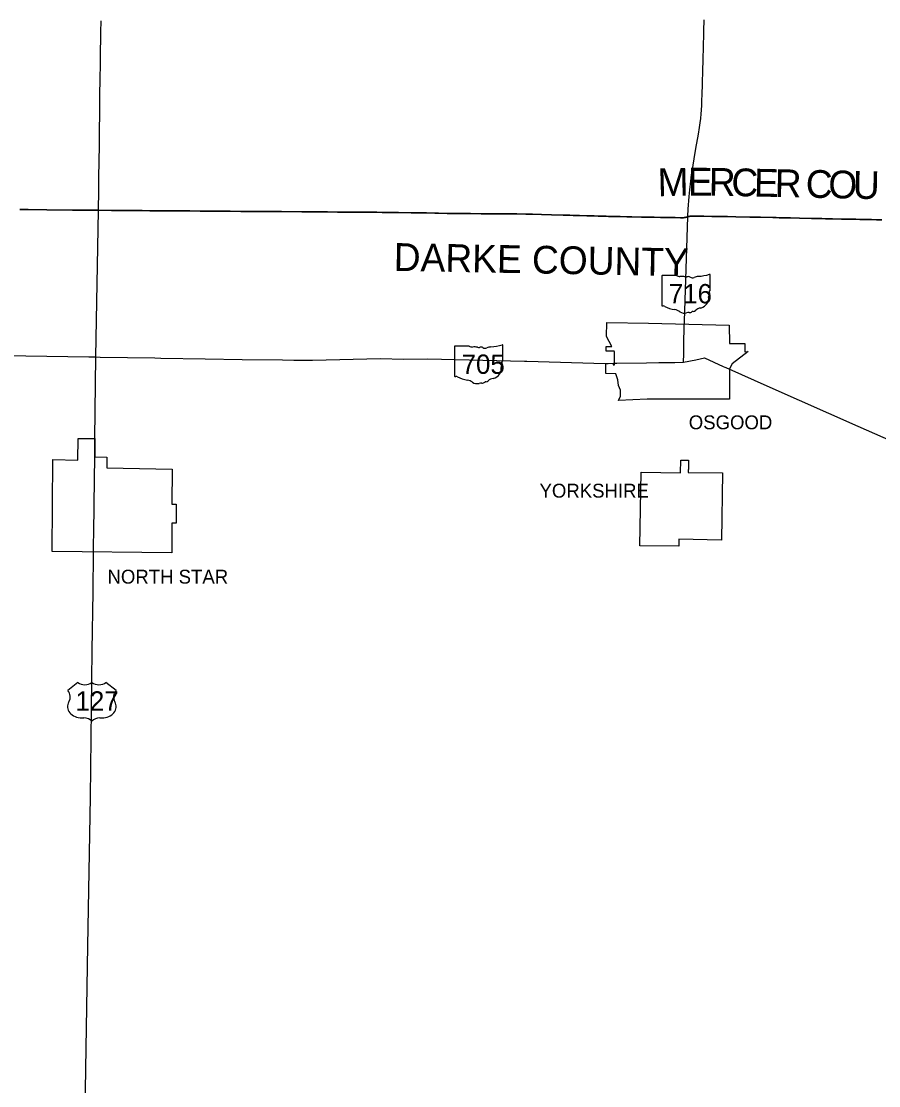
# Model space of a CAD drawing. Extents: x 0 to 34, y 0 to 22.
# Drawn here: x 3.621 to 4.117, y 18.175 to 18.791 of the extents above; entities that cross this region are included whole.
import ezdxf

# ---------------------------------------------------------------- set-up
doc = ezdxf.new("R2010")
doc.units = 0
for name, color, linetype in [('GM_X_Corporation', 7, 'Continuous'), ('GM_X_Corporation_Text', 7, 'Continuous'), ('GM_X_County', 7, 'Continuous'), ('GM_X_County_Text', 7, 'Continuous'), ('GM_X_State_Location', 7, 'Continuous'), ('GM_X_State_Route', 7, 'Continuous'), ('GM_X_State_Shield', 7, 'Continuous'), ('GM_X_US_Location', 7, 'Continuous'), ('GM_X_US_Route', 7, 'Continuous'), ('GM_X_US_Shield', 7, 'Continuous')]:
    doc.layers.add(name, color=color, linetype=linetype)

msp = doc.modelspace()

# ---------------------------------------------------------------- linework, layer by layer
at = {"layer": 'GM_X_Corporation'}
for points in [[(4.03961, 18.60404), (4.03961, 18.59925), (4.04143, 18.59956), (4.03216, 18.59229), (4.03063, 18.58941), (4.0307, 18.57198), (3.98295, 18.57181), (3.96632, 18.57122), (3.96758, 18.57369), (3.96764, 18.57718), (3.96634, 18.57985), (3.96604, 18.58315), (3.96488, 18.58654), (3.959, 18.58684), (3.95899, 18.59261), (3.96338, 18.59269), (3.9634, 18.59175), (3.96404, 18.59178), (3.96403, 18.59269), (3.96404, 18.59925), (3.96381, 18.59971), (3.96386, 18.59961), (3.95927, 18.59968), (3.95931, 18.60235), (3.96246, 18.60232), (3.95948, 18.60811), (3.95961, 18.61624), (3.98373, 18.61586), (4.03054, 18.61482), (4.03058, 18.6042)], [(3.67022, 18.53837), (3.67017, 18.53219), (3.70789, 18.53144), (3.70786, 18.51113), (3.71027, 18.51112), (3.71022, 18.50003), (3.70773, 18.50006), (3.70769, 18.48292), (3.63852, 18.48367), (3.63892, 18.53699), (3.65338, 18.53662), (3.65359, 18.54921), (3.66324, 18.54914), (3.66313, 18.53855)], [(3.97867, 18.48702), (3.97958, 18.5297), (4.00238, 18.5292), (4.00254, 18.5366), (4.00692, 18.5365), (4.00692, 18.5312), (4.00676, 18.5312), (4.00676, 18.52951), (4.02669, 18.52917), (4.02606, 18.49026), (4.00138, 18.49087), (4.00127, 18.48688), (3.97867, 18.48697)]]:
    msp.add_lwpolyline(points, close=True, dxfattribs=at)
at = {"layer": 'GM_X_County'}
for points in [[(4.11879, 18.67563), (4.11578, 18.6757), (4.1129, 18.6758), (4.10903, 18.67592), (4.10877, 18.67592), (4.10753, 18.67594), (4.10604, 18.67596), (4.10379, 18.676), (4.10186, 18.67604), (4.09543, 18.67616), (4.09031, 18.67627), (4.08615, 18.67634), (4.08404, 18.67638), (4.07819, 18.6765), (4.07128, 18.67664), (4.06594, 18.67676), (4.06248, 18.67684), (4.0595, 18.6769), (4.05763, 18.67695), (4.05749, 18.67695), (4.05569, 18.67699), (4.04861, 18.67715), (4.04247, 18.67725), (4.03427, 18.67744), (4.02952, 18.67753), (4.02652, 18.67758), (4.02372, 18.67763), (4.0204, 18.6777), (4.01587, 18.67777), (4.01215, 18.67786), (4.01025, 18.6779), (4.00974, 18.67791), (4.00912, 18.67791), (4.00885, 18.67791), (4.00863, 18.67789), (4.00839, 18.67787), (4.00821, 18.67784), (4.00798, 18.67781), (4.00771, 18.67776), (4.00744, 18.67771), (4.00716, 18.67764), (4.00692, 18.67757), (4.00671, 18.6775), (4.00645, 18.67743), (4.00636, 18.6774), (4.00609, 18.67732), (4.0058, 18.67724), (4.00546, 18.67716), (4.00518, 18.67709), (4.00491, 18.67704), (4.00465, 18.677), (4.0044, 18.67697), (4.00409, 18.67694), (4.00382, 18.67692), (4.00349, 18.67691), (4.00311, 18.67691), (4.00227, 18.67692), (3.99922, 18.67696), (3.99405, 18.67706), (3.99067, 18.67713), (3.98703, 18.67719), (3.9797, 18.67732), (3.97406, 18.67742), (3.97118, 18.67748), (3.96742, 18.67756), (3.96556, 18.6776), (3.96441, 18.67762), (3.96336, 18.67765), (3.9627, 18.67767), (3.96164, 18.67769), (3.96053, 18.67772), (3.96051, 18.67772), (3.95917, 18.67775), (3.95781, 18.67778), (3.95633, 18.67782), (3.95466, 18.67787), (3.95223, 18.67794), (3.95039, 18.67799), (3.94802, 18.67806), (3.9438, 18.67818), (3.94006, 18.6783), (3.93812, 18.67836), (3.93437, 18.67847), (3.92766, 18.67866), (3.92184, 18.67884), (3.91656, 18.679), (3.915, 18.67905), (3.91466, 18.67905), (3.91406, 18.67906), (3.91276, 18.67907), (3.90756, 18.6791), (3.90321, 18.67911), (3.89825, 18.67913), (3.89314, 18.67915), (3.88685, 18.67922), (3.88071, 18.67927), (3.87699, 18.6793), (3.87229, 18.67937), (3.86719, 18.67945), (3.86208, 18.67956), (3.86013, 18.67961), (3.85527, 18.67969), (3.84626, 18.67982), (3.83909, 18.67991), (3.83555, 18.67995), (3.83197, 18.67999), (3.8299, 18.68003), (3.82959, 18.68003), (3.82643, 18.68006), (3.82153, 18.68008), (3.81583, 18.68012), (3.81114, 18.68015), (3.80706, 18.68018), (3.80375, 18.6802), (3.7979, 18.68023), (3.794, 18.68025), (3.78858, 18.68028), (3.7831, 18.68033), (3.77132, 18.68043), (3.76958, 18.68044), (3.76072, 18.6805), (3.75418, 18.68054), (3.75107, 18.68056), (3.75, 18.68057), (3.74768, 18.68059), (3.74159, 18.68065), (3.73193, 18.68072), (3.72792, 18.68075), (3.72414, 18.68078), (3.71811, 18.68084), (3.71112, 18.68089), (3.70533, 18.68094), (3.69973, 18.68097), (3.69501, 18.681), (3.69058, 18.68104), (3.68121, 18.68113), (3.67281, 18.68118), (3.66525, 18.68121), (3.6601, 18.68127), (3.65023, 18.68138), (3.63536, 18.6815), (3.62466, 18.68161), (3.61981, 18.68166)], [(3.61981, 18.68166), (3.62466, 18.68161), (3.63536, 18.6815), (3.65023, 18.68138), (3.6601, 18.68127), (3.66525, 18.68121), (3.67281, 18.68118), (3.68121, 18.68113), (3.69058, 18.68104), (3.69501, 18.681), (3.69973, 18.68097), (3.70533, 18.68094), (3.71112, 18.68089), (3.71811, 18.68084), (3.72414, 18.68078), (3.72792, 18.68075), (3.73193, 18.68072), (3.74159, 18.68065), (3.74768, 18.68059), (3.75, 18.68057), (3.75107, 18.68056), (3.75418, 18.68054), (3.76072, 18.6805), (3.76958, 18.68044), (3.77132, 18.68043), (3.7831, 18.68033), (3.78858, 18.68028), (3.794, 18.68025), (3.7979, 18.68023), (3.80375, 18.6802), (3.80706, 18.68018), (3.81114, 18.68015), (3.81583, 18.68012), (3.82153, 18.68008), (3.82643, 18.68006), (3.82959, 18.68003), (3.8299, 18.68003), (3.83197, 18.67999), (3.83555, 18.67995), (3.83909, 18.67991), (3.84626, 18.67982), (3.85527, 18.67969), (3.86013, 18.67961), (3.86208, 18.67956), (3.86719, 18.67945), (3.87229, 18.67937), (3.87699, 18.6793), (3.88071, 18.67927), (3.88685, 18.67922), (3.89314, 18.67915), (3.89825, 18.67913), (3.90321, 18.67911), (3.90756, 18.6791), (3.91276, 18.67907), (3.91406, 18.67906), (3.91466, 18.67905), (3.915, 18.67905), (3.91656, 18.679), (3.92184, 18.67884), (3.92766, 18.67866), (3.93437, 18.67847), (3.93812, 18.67836), (3.94006, 18.6783), (3.9438, 18.67818), (3.94802, 18.67806), (3.95039, 18.67799), (3.95223, 18.67794), (3.95466, 18.67787), (3.95633, 18.67782), (3.95781, 18.67778), (3.95917, 18.67775), (3.96051, 18.67772), (3.96053, 18.67772), (3.96164, 18.67769), (3.9627, 18.67767), (3.96336, 18.67765), (3.96441, 18.67762), (3.96556, 18.6776), (3.96742, 18.67756), (3.97118, 18.67748), (3.97406, 18.67742), (3.9797, 18.67732), (3.98703, 18.67719), (3.99067, 18.67713), (3.99405, 18.67706), (3.99922, 18.67696), (4.00227, 18.67692), (4.00311, 18.67691), (4.00349, 18.67691), (4.00382, 18.67692), (4.00409, 18.67694), (4.0044, 18.67697), (4.00465, 18.677), (4.00491, 18.67704), (4.00518, 18.67709), (4.00546, 18.67716), (4.0058, 18.67724), (4.00609, 18.67732), (4.00636, 18.6774), (4.00645, 18.67743), (4.00671, 18.6775), (4.00692, 18.67757), (4.00716, 18.67764), (4.00744, 18.67771), (4.00771, 18.67776), (4.00798, 18.67781), (4.00821, 18.67784), (4.00839, 18.67787), (4.00863, 18.67789), (4.00885, 18.67791), (4.00912, 18.67791), (4.00974, 18.67791), (4.01025, 18.6779), (4.01215, 18.67786), (4.01587, 18.67777), (4.0204, 18.6777), (4.02372, 18.67763), (4.02652, 18.67758), (4.02952, 18.67753), (4.03427, 18.67744), (4.04247, 18.67725), (4.04861, 18.67715), (4.05569, 18.67699), (4.05749, 18.67695), (4.05763, 18.67695), (4.0595, 18.6769), (4.06248, 18.67684), (4.06594, 18.67676), (4.07128, 18.67664), (4.07819, 18.6765), (4.08404, 18.67638), (4.08615, 18.67634), (4.09031, 18.67627), (4.09543, 18.67616), (4.10186, 18.67604), (4.10379, 18.676), (4.10604, 18.67596), (4.10753, 18.67594), (4.10877, 18.67592), (4.10903, 18.67592), (4.1129, 18.6758), (4.11578, 18.6757), (4.11879, 18.67563)]]:
    msp.add_lwpolyline(points, dxfattribs=at)
at = {"layer": 'GM_X_State_Route'}
for p, q in [((4.00455, 18.61709), (4.00647, 18.67738)), ((3.65963, 18.5964), (3.66378, 18.59633)), ((3.66378, 18.59633), (3.66634, 18.59629)), ((3.66634, 18.59629), (3.69799, 18.59576)), ((3.69799, 18.59576), (3.70141, 18.5957)), ((3.77179, 18.59463), (3.77847, 18.59455))]:
    msp.add_line(p, q, dxfattribs=at)
for points in [[(4.00647, 18.67738), (4.0065, 18.67785), (4.00671, 18.68188), (4.00726, 18.68914), (4.00766, 18.69302), (4.00824, 18.69799), (4.00872, 18.70165), (4.00919, 18.70484), (4.01062, 18.71358), (4.01157, 18.71902), (4.01176, 18.72012), (4.01264, 18.72532), (4.0133, 18.72917), (4.0137, 18.73189), (4.014, 18.7343), (4.0143, 18.73713), (4.01445, 18.73913), (4.0146, 18.74203), (4.01466, 18.74415), (4.01466, 18.74435), (4.01478, 18.74867), (4.01496, 18.75384), (4.01505, 18.75674), (4.01516, 18.76022), (4.01543, 18.76997), (4.01557, 18.77429), (4.01587, 18.7851), (4.01605, 18.79137)], [(4.00404, 18.59326), (4.00414, 18.59816), (4.00428, 18.6046), (4.00447, 18.61347), (4.00447, 18.61364)], [(4.00447, 18.61364), (4.00454, 18.61684), (4.00455, 18.61709)], [(3.47309, 18.59233), (3.49425, 18.59176), (3.53449, 18.59069), (3.53572, 18.59095), (3.53626, 18.59167), (3.53631, 18.59245), (3.5366, 18.59827), (3.55784, 18.59794), (3.58258, 18.59756), (3.62317, 18.59694), (3.65963, 18.5964)], [(3.70141, 18.5957), (3.72707, 18.59527), (3.74841, 18.59491), (3.77179, 18.59463)], [(3.77847, 18.59455), (3.78924, 18.59442), (3.82864, 18.59551), (3.842, 18.59512), (3.85572, 18.59521), (3.91188, 18.59397), (3.91323, 18.59393)], [(3.91323, 18.59393), (3.95867, 18.59257), (3.95949, 18.59258), (3.96033, 18.5926)], [(4.00404, 18.59326), (4.01122, 18.59475), (4.01609, 18.59576), (4.02709, 18.59088)], [(3.96033, 18.5926), (3.96378, 18.59265), (3.96455, 18.59266)], [(3.96455, 18.59266), (3.96463, 18.59266), (3.96539, 18.59267)], [(3.96539, 18.59267), (3.98262, 18.59293), (3.98976, 18.59304)], [(3.98976, 18.59304), (3.9922, 18.59308), (3.99906, 18.59318), (4.00404, 18.59326)], [(4.02709, 18.59088), (4.02793, 18.5905), (4.02862, 18.5902)], [(4.02862, 18.5902), (4.05399, 18.57893), (4.10501, 18.55629), (4.14042, 18.54057)]]:
    msp.add_lwpolyline(points, dxfattribs=at)
at = {"layer": 'GM_X_State_Shield'}
for p, q in [((3.99151, 18.64315), (3.99151, 18.62616)), ((3.99998, 18.64344), (3.99178, 18.64344)), ((4.01948, 18.63498), (4.01948, 18.64386)), ((4.01948, 18.63498), (4.01948, 18.63498)), ((3.87142, 18.60234), (3.87142, 18.58535)), ((3.87988, 18.60263), (3.87169, 18.60263)), ((3.89939, 18.59417), (3.89939, 18.60305)), ((3.89939, 18.59417), (3.89939, 18.59417))]:
    msp.add_line(p, q, dxfattribs=at)
for centre, major_axis, start_param, end_param in [((3.99183, 18.64318), (0.000324, 0), 1.712693, 3.28349), ((4.00193, 18.64541), (0.00314, 0), 4.042523, 4.731795), ((4.00297, 18.6339), (0.01128, 0), 1.404758, 1.657858), ((4.0133, 18.63825), (0.00597, 0), 1.699011, 2.107814), ((4.00952, 18.6666), (0.02966, 0), 4.814394, 5.042369), ((4.01917, 18.6439), (0.000311, 0), 6.141152, 7.989035), ((4.00553, 18.64327), (0.000907, 0), 3.836095, 5.185415), ((4.00686, 18.64131), (0.00189, 0), 0.950623, 2.079405), ((4.0093, 18.644), (0.00227, 0), 4.081561, 5.145723), ((4.01118, 18.63013), (0.00742, 0), 5.101752, 6.440018), ((4.0206, 18.63126), (0.0021, 0), 2.387724, 3.262537), ((4.01941, 18.63432), (0.000482, 0), 1.883978, 3.671073), ((4.01634, 18.6332), (0.00289, 0), 5.934695, 6.695948), ((4.01915, 18.63494), (0.000333, 0), 5.05454, 6.418171), ((3.99183, 18.62613), (0.000327, 0), 3.00124, 4.508301), ((3.99188, 18.62786), (0.00249, 0), 4.665946, 4.897461), ((3.99239, 18.62518), (0.0009, 0), 0.519207, 1.627899), ((4.00375, 18.64044), (0.02142, 0), 4.195997, 4.488961), ((4.01431, 18.62139), (0.00406, 0), 1.647645, 2.488434), ((3.99736, 18.61853), (0.0067, 0), 0.823519, 1.323587), ((4.00461, 18.6251), (0.00425, 0), 4.026481, 4.996735), ((4.00707, 18.61923), (0.00349, 0), 1.495662, 1.94098), ((4.00738, 18.62383), (0.00227, 0), 4.691044, 5.507374), ((4.00943, 18.62218), (0.000638, 0), 1.147584, 2.315152), ((4.00916, 18.62452), (0.0024, 0), 4.937069, 5.64225), ((3.87174, 18.60237), (0.000324, 0), 1.712693, 3.28349), ((3.88184, 18.6046), (0.00314, 0), 4.042523, 4.731795), ((3.88288, 18.5931), (0.01128, 0), 1.404758, 1.657858), ((3.88544, 18.60246), (0.000907, 0), 3.836095, 5.185415), ((3.88677, 18.6005), (0.00189, 0), 0.950623, 2.079405), ((3.8892, 18.60319), (0.00227, 0), 4.081561, 5.145723), ((3.89321, 18.59744), (0.00597, 0), 1.699011, 2.107814), ((3.88943, 18.62579), (0.02966, 0), 4.814394, 5.042369), ((3.89908, 18.60309), (0.000311, 0), 6.141152, 7.989035), ((3.89932, 18.59351), (0.000482, 0), 1.883978, 3.671073), ((3.89906, 18.59413), (0.000333, 0), 5.05454, 6.418171), ((3.89109, 18.58932), (0.00742, 0), 5.101752, 6.440018), ((3.9005, 18.59045), (0.0021, 0), 2.387724, 3.262537), ((3.89625, 18.59239), (0.00289, 0), 5.934695, 6.695948), ((3.87174, 18.58532), (0.000327, 0), 3.00124, 4.508301), ((3.87179, 18.58705), (0.00249, 0), 4.665946, 4.897461), ((3.8723, 18.58437), (0.0009, 0), 0.519207, 1.627899), ((3.88366, 18.59963), (0.02142, 0), 4.195997, 4.488961), ((3.87727, 18.57772), (0.0067, 0), 0.823519, 1.323587), ((3.88452, 18.58429), (0.00425, 0), 4.026481, 4.996735), ((3.88729, 18.58302), (0.00227, 0), 4.691044, 5.507374), ((3.88934, 18.58137), (0.000638, 0), 1.147584, 2.315152), ((3.88907, 18.58371), (0.0024, 0), 4.937069, 5.64225), ((3.89422, 18.58059), (0.00406, 0), 1.647645, 2.488434), ((3.88698, 18.57842), (0.00349, 0), 1.495662, 1.94098)]:
    msp.add_ellipse(centre, major_axis=major_axis, ratio=0.8, start_param=start_param, end_param=end_param, dxfattribs=at)
at = {"layer": 'GM_X_US_Route'}
for p, q in [((3.66313, 18.53873), (3.66325, 18.54905)), ((3.66268, 18.49934), (3.66276, 18.50527)), ((3.66246, 18.48324), (3.66268, 18.49934)), ((3.66217, 18.46036), (3.66246, 18.48324))]:
    msp.add_line(p, q, dxfattribs=at)
for points in [[(3.66527, 18.68116), (3.66544, 18.69295), (3.66554, 18.70033), (3.66582, 18.71868), (3.66583, 18.72216), (3.66586, 18.72356), (3.6659, 18.72538), (3.66608, 18.73914), (3.66618, 18.7479), (3.66631, 18.75729), (3.66639, 18.76579), (3.66644, 18.76815), (3.66651, 18.77416), (3.66662, 18.77965), (3.66667, 18.78423), (3.66679, 18.79088)], [(3.66325, 18.54905), (3.66378, 18.59633), (3.66527, 18.68116)], [(3.66276, 18.50527), (3.66284, 18.5112), (3.66313, 18.53873)], [(3.66075, 18.34159), (3.66172, 18.42646), (3.66217, 18.46036)], [(3.65792, 18.18426), (3.65913, 18.2554), (3.66075, 18.34159)], [(3.62959, 17.92225), (3.63119, 17.92818), (3.63497, 17.93997), (3.63868, 17.95151), (3.64315, 17.96501), (3.64965, 17.98529), (3.65607, 18.00649), (3.65766, 18.01542), (3.65766, 18.01703), (3.65759, 18.05745), (3.65763, 18.09241), (3.65771, 18.17171), (3.65792, 18.18426)]]:
    msp.add_lwpolyline(points, dxfattribs=at)
at = {"layer": 'GM_X_US_Shield'}
for p, q in [((3.65334, 18.40793), (3.64751, 18.40327)), ((3.67548, 18.40327), (3.66965, 18.40793)), ((3.65567, 18.38741), (3.65683, 18.38741)), ((3.66616, 18.38741), (3.66732, 18.38741))]:
    msp.add_line(p, q, dxfattribs=at)
for centre, major_axis, start_param, end_param in [((3.64082, 18.39952), (0.00816, 0), 5.838949, 6.894067), ((3.65741, 18.41126), (-0.00583, 0), 0.795399, 2.346194), ((3.66557, 18.41126), (-0.00583, 0), 0.795399, 2.346194), ((3.68216, 18.39952), (-0.00816, 0), 5.672304, 6.727422), ((3.65558, 18.39394), (0.00816, 0), 2.702327, 4.723529), ((3.66741, 18.39394), (-0.00816, 0), 1.559657, 3.580859), ((3.65683, 18.38275), (-0.00583, 0), 3.785094, 4.712389), ((3.66616, 18.38275), (-0.00583, 0), 4.712389, 5.639684)]:
    msp.add_ellipse(centre, major_axis=major_axis, ratio=0.8, start_param=start_param, end_param=end_param, dxfattribs=at)

# ---------------------------------------------------------------- texts
at = {"layer": 'GM_X_Corporation_Text'}
for s, p in [('OSGOOD', (4.00707, 18.55447)), ('YORKSHIRE', (3.92066, 18.5149)), ('NORTH STAR', (3.67052, 18.46514))]:
    msp.add_text(s, height=0.008037, rotation=0.00001, dxfattribs=at).set_placement(p)
at = {"layer": 'GM_X_County_Text'}
for s, height, rotation, p in [('M', 0.01607, 1.36838, (3.98923, 18.68932)), ('E', 0.01607, 359.91225, (4.00659, 18.68974)), ('R', 0.01607, 359.0424, (4.01855, 18.68972)), ('C', 0.01607, 358.76737, (4.03161, 18.6895)), ('E', 0.01607, 358.75665, (4.04469, 18.68922)), ('R', 0.01607, 358.75643, (4.05671, 18.68896)), ('C', 0.01607, 358.75614, (4.07467, 18.68857)), ('O', 0.01607, 358.75686, (4.08775, 18.68829)), ('U', 0.01607, 358.75647, (4.10197, 18.68798)), ('DARKE COUNTY', 0.016074, 358.9262, (3.83616, 18.64621))]:
    msp.add_text(s, height=height, rotation=rotation, dxfattribs=at).set_placement(p)
at = {"layer": 'GM_X_State_Location'}
for s, p in [('716', (3.99951, 18.63236)), ('705', (3.87941, 18.59155))]:
    msp.add_text(s, height=0.0000161, rotation=0.00001, dxfattribs=at).set_placement(p)
for s, p in [('s', (4.00518, 18.63353)), ('r', (4.00518, 18.63353)), ('s', (3.88509, 18.59272)), ('r', (3.88509, 18.59272))]:
    msp.add_text(s, height=0.0000161, dxfattribs=at).set_placement(p)
at = {"layer": 'GM_X_State_Shield'}
for s, p in [('716', (3.99553, 18.62736)), ('705', (3.87559, 18.58655))]:
    msp.add_text(s, height=0.011189, dxfattribs=at).set_placement(p)
at = {"layer": 'GM_X_US_Location'}
for s in ['0', '/']:
    msp.add_text(s, height=0.0000161, dxfattribs=at).set_placement((3.6615, 18.3972))
msp.add_text('127', height=0.0000161, rotation=0.00001, dxfattribs=at).set_placement((3.65656, 18.39387))
at = {"layer": 'GM_X_US_Shield'}
msp.add_text('127', height=0.011189, dxfattribs=at).set_placement((3.652, 18.39161))

doc.saveas('drawing.dxf')
